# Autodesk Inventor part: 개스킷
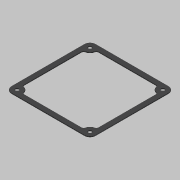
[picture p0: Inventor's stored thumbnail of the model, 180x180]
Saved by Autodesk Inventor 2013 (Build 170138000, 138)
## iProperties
Created: 2019-04
Part Number: 개스킷
Material: 고무
Document SubType Name: Modeling
Designer: mduedu
Density: 0.93 g/cm^3
Mass: 2.32152 g
Surface Area: 58.0824 cm^2
Volume: 2.49626 cm^3
Author: mduedu
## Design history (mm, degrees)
sketch "스케치1"
  geometry: L1 (52.5, 52.5)-(-52.5, 52.5); L2 (-52.5, 52.5)-(-52.5, -52.5); L3 (-52.5, -52.5)-(52.5, -52.5); L4 (52.5, -52.5)-(52.5, 52.5); L5 (52.5, 52.5)-(-52.5, -52.5); L6 (-52.5, 52.5)-(52.5, -52.5); 1 further point
  constraints: 12 end point, 2 midpoint, 2 parallel, 1 horizontal, 1 perpendicular
  dimensions: "d0" = 105 distance of L3.end L2.end; "d1" = 105 distance of L2.end L1.end
extrude "돌출1" new body sketch "스케치1" distance "d2" = 1; taper "d3" = 0 deg
sketch "스케치2"
  geometry: L1 (-52.5, -52.5)-(52.5, -52.5) reference; L2 (52.5, -52.5)-(52.5, 52.5) reference; L3 (52.5, 52.5)-(-52.5, 52.5) reference; L4 (-52.5, 52.5)-(-52.5, -52.5) reference; L5 (-46.5, 46.5)-(46.5, 46.5); L6 (46.5, 46.5)-(46.5, -46.5); L7 (46.5, -46.5)-(-46.5, -46.5); L8 (-46.5, -46.5)-(-46.5, 46.5); 1 further point
  constraints: 8 end point, 3 other
  dimensions: "d4" = 6 distance between parallel lines of L5 L3
extrude "돌출2" cut sketch "스케치2" stored distance "d5" = 1; taper "d6" = 0 deg
fillet "모깎기1" dims "d7" = 7
sketch "스케치3"
  geometry: A1 r 7 centre (-45.5, 45.5) between (-45.5, 52.5) and (-52.5, 45.5) reference; A2 r 7 centre (-45.5, -45.5) between (-52.5, -45.5) and (-45.5, -52.5) reference; A3 r 7 centre (45.5, -45.5) between (45.5, -52.5) and (52.5, -45.5) reference; A4 r 7 centre (45.5, 45.5) between (52.5, 45.5) and (45.5, 52.5) reference; 5 further points
  constraints: 4 coincident, 4 vertical alignment, 8 other
extrude "돌출3" join sketch "스케치3" stored distance "d8" = 1; taper "d9" = 0 deg
fillet "모깎기2" dims "d10" = 3
sketch "스케치4"
  geometry: A1 r 7 centre (-45.5, 45.5) between (-45.5, 52.5) and (-52.5, 45.5) reference; A2 r 7 centre (45.5, 45.5) between (52.5, 45.5) and (45.5, 52.5) reference; A3 r 7 centre (45.5, -45.5) between (45.5, -52.5) and (52.5, -45.5) reference; A4 r 7 centre (-45.5, -45.5) between (-52.5, -45.5) and (-45.5, -52.5) reference; 5 further points
  constraints: 4 coincident
hole "구멍1" sketch "스케치4" at (-45.5, 45.5), (45.5, 45.5), (45.5, -45.5), (-45.5, -45.5) diameter "d11" = 4.5; stored, may be unused: countersink angle "d15" = 90 deg, drill point angle "d17" = 118 deg; dims "d12" = 6, "d13" = 4, "d14" = 2, "d16" = 8
node "솔리드1"
node "투영된 루프1"
